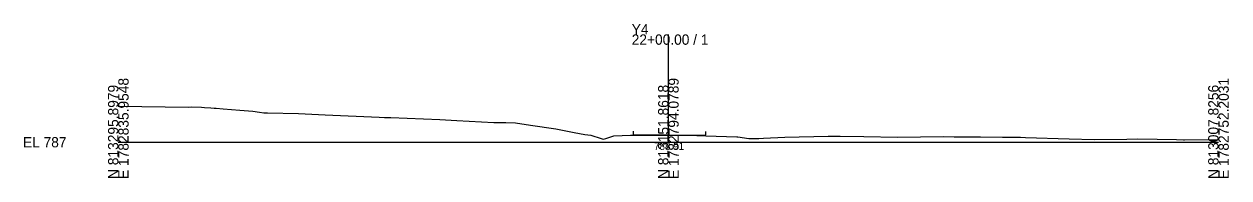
# Model space of a CAD drawing. Extents: x -26 to 3903, y -10 to 9562.
# Drawn here: x 974.3 to 1302.8, y 4490.3 to 4532.1 of the extents above; entities that cross this region are included whole.
import ezdxf

# ---------------------------------------------------------------- set-up
doc = ezdxf.new("R2010")
doc.units = 0
for name, color, linetype in [('Exist Cross Section Cell', 7, 'Continuous'), ('Exist XS Center Line Elevation Label', 7, 'Continuous'), ('Exist XS Ground Line', 7, 'Continuous'), ('Prop XS EOT Tick Mark', 7, 'Continuous'), ('Prop XS Finish Grade Pavement', 7, 'Continuous')]:
    doc.layers.add(name, color=color, linetype=linetype)

msp = doc.modelspace()

# ---------------------------------------------------------------- linework, layer by layer
at = {"layer": 'Exist Cross Section Cell'}
for p, q in [((1150, 4500), (1150, 4529.32)), ((1000, 4500), (1150, 4500)), ((1150, 4500), (1300, 4500))]:
    msp.add_line(p, q, dxfattribs=at)
at = {"layer": 'Exist XS Ground Line'}
for p, q in [((1000, 4509.77), (1019.19, 4509.58)), ((1019.19, 4509.58), (1019.94, 4509.62)), ((1019.94, 4509.62), (1022.71, 4509.54)), ((1022.71, 4509.54), (1023.53, 4509.47)), ((1023.53, 4509.47), (1025.21, 4509.36)), ((1025.21, 4509.36), (1026.12, 4509.26)), ((1026.12, 4509.26), (1026.69, 4509.22)), ((1026.69, 4509.22), (1028.55, 4509.07)), ((1028.55, 4509.07), (1033.09, 4508.72)), ((1033.09, 4508.72), (1036.72, 4508.45)), ((1036.72, 4508.45), (1038.54, 4508.19)), ((1038.54, 4508.19), (1039.67, 4508.03)), ((1039.67, 4508.03), (1040.64, 4508.02)), ((1040.64, 4508.02), (1049.16, 4507.77)), ((1049.16, 4507.77), (1056.41, 4507.45)), ((1056.41, 4507.45), (1071.17, 4506.83)), ((1071.17, 4506.83), (1072.59, 4506.76)), ((1072.59, 4506.76), (1074.31, 4506.71)), ((1074.31, 4506.71), (1087.67, 4506.22)), ((1087.67, 4506.22), (1092.29, 4505.89)), ((1092.29, 4505.89), (1102.42, 4505.4)), ((1102.42, 4505.4), (1105.71, 4505.38)), ((1105.71, 4505.38), (1108.34, 4505.26)), ((1108.34, 4505.26), (1112.43, 4504.65)), ((1112.43, 4504.65), (1119.29, 4503.61)), ((1119.29, 4503.61), (1121.99, 4503.11)), ((1121.99, 4503.11), (1124.3, 4502.66)), ((1124.3, 4502.66), (1127.17, 4502.08)), ((1127.17, 4502.08), (1128.82, 4501.88)), ((1128.82, 4501.88), (1131.7, 4501.02)), ((1131.7, 4501.02), (1132.24, 4500.81)), ((1132.24, 4500.81), (1132.94, 4500.99)), ((1132.94, 4500.99), (1135.16, 4501.78)), ((1135.16, 4501.78), (1139.65, 4501.88)), ((1139.65, 4501.88), (1140.42, 4501.88)), ((1140.42, 4501.88), (1143.1, 4501.89)), ((1143.1, 4501.89), (1150.24, 4501.91)), ((1150.24, 4501.91), (1157.79, 4501.79)), ((1157.79, 4501.79), (1160.23, 4501.75)), ((1160.23, 4501.75), (1168.64, 4501.46)), ((1168.64, 4501.46), (1168.95, 4501.44)), ((1168.95, 4501.44), (1171.92, 4501)), ((1171.92, 4501), (1174.7, 4501)), ((1174.7, 4501), (1175.97, 4501.13)), ((1175.97, 4501.13), (1181.72, 4501.34)), ((1181.72, 4501.34), (1193.53, 4501.61)), ((1193.53, 4501.61), (1196.86, 4501.65)), ((1196.86, 4501.65), (1203.29, 4501.54)), ((1203.29, 4501.54), (1212.46, 4501.38)), ((1212.46, 4501.38), (1225.01, 4501.52)), ((1225.01, 4501.52), (1227.91, 4501.49)), ((1227.91, 4501.49), (1235.08, 4501.48)), ((1235.08, 4501.48), (1241.1, 4501.39)), ((1241.1, 4501.39), (1246.04, 4501.34)), ((1246.04, 4501.34), (1247.38, 4501.28)), ((1247.38, 4501.28), (1259.32, 4500.96)), ((1259.32, 4500.96), (1266.07, 4500.71)), ((1266.07, 4500.71), (1275.01, 4500.85)), ((1275.01, 4500.85), (1278.05, 4500.9)), ((1278.05, 4500.9), (1288.58, 4500.71)), ((1288.58, 4500.71), (1290.42, 4500.69)), ((1290.42, 4500.69), (1290.77, 4500.68)), ((1290.77, 4500.68), (1300, 4500.7))]:
    msp.add_line(p, q, dxfattribs=at)
at = {"layer": 'Prop XS EOT Tick Mark'}
for p, q in [((1140.45, 4502), (1140.45, 4503)), ((1160.24, 4501.88), (1160.24, 4502.88))]:
    msp.add_line(p, q, dxfattribs=at)
at = {"layer": 'Prop XS Finish Grade Pavement'}
for p, q in [((1140.45, 4502), (1143.1, 4502.02)), ((1143.1, 4502.02), (1150.24, 4502.04)), ((1150.24, 4502.04), (1157.79, 4501.92)), ((1157.79, 4501.92), (1160.23, 4501.88)), ((1160.23, 4501.88), (1160.24, 4501.88))]:
    msp.add_line(p, q, dxfattribs=at)

# ---------------------------------------------------------------- texts
at = {"layer": 'Exist Cross Section Cell'}
for s, p in [('Y4', (1140, 4529.32)), ('22+00.00 / 1', (1140, 4526.52)), ('EL 787', (974, 4498.6))]:
    msp.add_text(s, height=2.8, dxfattribs=at).set_placement(p)
for s, p in [('N 813295.8979', (1000, 4490)), ('E 1782835.9548', (1002.8, 4490)), ('N 813151.8618', (1150, 4490)), ('E 1782794.0789', (1152.8, 4490)), ('N 813007.8256', (1300, 4490)), ('E 1782752.2031', (1302.8, 4490))]:
    msp.add_text(s, height=2.8, rotation=90, dxfattribs=at).set_placement(p)
at = {"layer": 'Exist XS Center Line Elevation Label'}
msp.add_text('788.91', height=2, dxfattribs=at).set_placement((1146.08, 4497.91))

doc.saveas('drawing.dxf')
